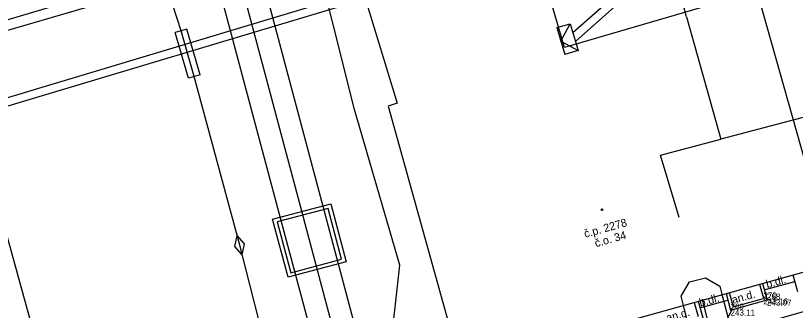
# Model space of a CAD drawing. Extents: x -599432 to -598680, y -1159407 to -1158632.
# Drawn here: x -599144.96 to -599106.02, y -1158898.71 to -1158883.97 of the extents above; entities that cross this region are included whole.
import ezdxf

# ---------------------------------------------------------------- set-up
doc = ezdxf.new("R2010")
doc.units = 0
for name, color, linetype in [('0004 VY - Body podrobné', 7, 'Continuous'), ('0005 VY - Body podrobné - čísla', 7, 'Continuous'), ('0006 VY - Body podrobné - výšky', 7, 'Continuous'), ('0007 ZA - Budova - zděná', 7, 'Continuous'), ('0009 TE - Budova - popis', 7, 'Continuous'), ('0010 ZA - Budova - označení', 7, 'Continuous'), ('0031 ZA - Ostatní rozhraní', 7, 'Continuous'), ('0032 TE - Popis povrchu', 7, 'Continuous'), ('0049 TE - Orientační _ popisná čísla', 7, 'Continuous'), ('0116 PV - budova převzatá z mapy', 7, 'Continuous'), ('0250 PV - TB - buňky', 7, 'Continuous'), ('0254 PV - TB - horkovod - vedení', 7, 'Continuous'), ('0255 PV - TB - horkovod - okraj', 7, 'Continuous'), ('0265 PV - TB - cizí síť vedení', 7, 'Continuous'), ('0266 PV - TB - cizí síť okraj', 7, 'Continuous'), ('0303 PV - RWE - NTL přípojka', 7, 'Continuous'), ('0308 PV - RWE - ochranné pásmo', 7, 'Continuous'), ('0350 PV - EON - buňky', 7, 'Continuous'), ('0352 PV - EON - NN', 7, 'Continuous'), ('0454 PV - O2 - kabel zaměřený', 7, 'Continuous'), ('0454 PV - PODA -  vedeni budoucnost', 7, 'Continuous'), ('0455 PV - O2 - kabel nezaměřený', 7, 'Continuous'), ('0551 PV - NETBOX - buňky', 7, 'Continuous'), ('0552 PV - NETBOX - vedení', 7, 'Continuous'), ('0553 PV - NETBOX - chranička', 7, 'Continuous')]:
    doc.layers.add(name, color=color, linetype=linetype)

# ---------------------------------------------------------------- blocks, each defined once
blk = doc.blocks.new('NN630')
at = {"layer": '0009 TE - Budova - popis'}
for points in [[(-0.003, -0.7), (-0.703, 0)], [(-0.703, -0.7), (-0.703, 0), (0.697, 0), (0.697, -0.7)], [(-0.003, -0.7), (0.697, 0)], [(-0.703, -0.7), (0.697, -0.7)]]:
    blk.add_lwpolyline(points, dxfattribs=at)

msp = doc.modelspace()

# ---------------------------------------------------------------- linework, layer by layer
at = {"layer": '0004 VY - Body podrobné'}
for p, q in [((-599106.03, -1158897.26), (-599106.03, -1158897.26)), ((-599107.62, -1158898.11), (-599107.62, -1158898.11)), ((-599107.44, -1158898.17), (-599107.44, -1158898.17)), ((-599109.26, -1158898.67), (-599109.26, -1158898.67))]:
    msp.add_line(p, q, dxfattribs=at)
at = {"layer": '0007 ZA - Budova - zděná'}
msp.add_line((-599122.72, -1158901.55), (-599062.29, -1158884.74), dxfattribs=at)
at = {"layer": '0010 ZA - Budova - označení'}
msp.add_circle((-599115.676, -1158893.68), 0.0438, dxfattribs=at)
at = {"layer": '0031 ZA - Ostatní rozhraní'}
for p, q in [((-599106.14, -1158896.938), (-599105.91, -1158897.767)), ((-599107.816, -1158897.404), (-599107.621, -1158898.107)), ((-599107.665, -1158897.362), (-599107.434, -1158898.191)), ((-599107.574, -1158897.689), (-599106.049, -1158897.265)), ((-599109.483, -1158897.868), (-599109.253, -1158898.697)), ((-599109.329, -1158897.825), (-599109.133, -1158898.528)), ((-599111.074, -1158898.31), (-599110.878, -1158899.014)), ((-599110.879, -1158898.256), (-599110.649, -1158899.085)), ((-599110.788, -1158898.584), (-599109.392, -1158898.195)), ((-599109.253, -1158898.697), (-599107.434, -1158898.191)), ((-599109.133, -1158898.531), (-599107.62, -1158898.11))]:
    msp.add_line(p, q, dxfattribs=at)
at = {"layer": '0032 TE - Popis povrchu'}
msp.add_line((-599109.68, -1158899.585), (-599109.146, -1158898.614), dxfattribs=at)
at = {"layer": '0116 PV - budova převzatá z mapy'}
for p, q in [((-599117.55, -1158885.56), (-599118.83, -1158881.17)), ((-599107.93, -1158882.74), (-599117.55, -1158885.56)), ((-599104.106, -1158896.372), (-599107.93, -1158882.74)), ((-599127.37, -1158883.54), (-599125.91, -1158888.34)), ((-599125.91, -1158888.34), (-599126.36, -1158888.49)), ((-599126.36, -1158888.49), (-599122.72, -1158901.55)), ((-599145.8, -1158893.59), (-599142.02, -1158907.12))]:
    msp.add_line(p, q, dxfattribs=at)
at = {"layer": '0250 PV - TB - buňky'}
for points in [[(-599132.129, -1158894.153), (-599129.224, -1158893.379), (-599128.45, -1158896.283), (-599131.354, -1158897.058), (-599132.129, -1158894.153)], [(-599131.221, -1158896.828), (-599128.68, -1158896.15), (-599129.357, -1158893.609), (-599131.899, -1158894.286), (-599131.221, -1158896.828)]]:
    msp.add_lwpolyline(points, dxfattribs=at)
at = {"layer": '0254 PV - TB - horkovod - vedení'}
msp.add_line((-599130.737, -1158893.547), (-599118.2, -1158940.655), dxfattribs=at)
at = {"layer": '0255 PV - TB - horkovod - okraj'}
for p, q in [((-599129.678, -1158893.249), (-599117.137, -1158940.372)), ((-599119.456, -1158940.213), (-599131.796, -1158893.845))]:
    msp.add_line(p, q, dxfattribs=at)
at = {"layer": '0265 PV - TB - cizí síť vedení'}
msp.add_lwpolyline([(-599093.332, -1158833.645), (-599087.354, -1158856.106), (-599137.173, -1158869.365), (-599130.737, -1158893.547)], dxfattribs=at)
at = {"layer": '0266 PV - TB - cizí síť okraj'}
for points in [[(-599092.269, -1158833.361), (-599086.008, -1158856.886), (-599135.827, -1158870.145), (-599129.678, -1158893.249)], [(-599131.796, -1158893.845), (-599138.519, -1158868.585), (-599088.7, -1158855.326), (-599094.395, -1158833.93)]]:
    msp.add_lwpolyline(points, dxfattribs=at)
at = {"layer": '0303 PV - RWE - NTL přípojka'}
msp.add_lwpolyline([(-599109.28, -1158903.4), (-599110.42, -1158899.1), (-599110.66, -1158898.15)], dxfattribs=at)
at = {"layer": '0308 PV - RWE - ochranné pásmo'}
msp.add_lwpolyline([(-599110.141, -1158904.057), (-599110.247, -1158903.656), (-599111.388, -1158899.351), (-599111.63, -1158898.395), (-599111.731, -1158897.993), (-599111.306, -1158897.281), (-599110.905, -1158897.18), (-599110.503, -1158897.079), (-599109.791, -1158897.504), (-599109.69, -1158897.905), (-599109.452, -1158898.849), (-599108.313, -1158903.144), (-599108.207, -1158903.544), (-599108.623, -1158904.261), (-599109.024, -1158904.367), (-599109.424, -1158904.473)], close=True, dxfattribs=at)
at = {"layer": '0352 PV - EON - NN'}
for points in [[(-599062.564, -1158867.124), (-599064.221, -1158867.572), (-599065.282, -1158867.859), (-599068.073, -1158869.751), (-599073.371, -1158871.463), (-599079.661, -1158873.298), (-599080.543, -1158872.51), (-599080.963, -1158873.779), (-599090.093, -1158876.254), (-599100.529, -1158879.074), (-599100.027, -1158880.841), (-599100.219, -1158880.896), (-599100.412, -1158880.951), (-599100.916, -1158879.178), (-599112.998, -1158882.403), (-599113.348, -1158881.982), (-599115.063, -1158882.464), (-599118.917, -1158878), (-599126.462, -1158879.719), (-599127.957, -1158880.989), (-599127.86, -1158882.798), (-599146.38, -1158888.373)], [(-599146.584, -1158888.851), (-599127.444, -1158883.09), (-599127.547, -1158881.165), (-599126.278, -1158880.087), (-599119.063, -1158878.444), (-599115.498, -1158882.572), (-599115.1, -1158883.033), (-599115.196, -1158883.118), (-599117.128, -1158884.834), (-599117.065, -1158885.046), (-599117.003, -1158885.259), (-599114.732, -1158883.24), (-599114.873, -1158882.827), (-599113.49, -1158882.438), (-599113.142, -1158882.855), (-599100.728, -1158879.542)]]:
    msp.add_lwpolyline(points, dxfattribs=at)
at = {"layer": '0454 PV - O2 - kabel zaměřený'}
msp.add_lwpolyline([(-599111.46, -1158884.03), (-599113.74, -1158875.43), (-599119.34, -1158876.95), (-599128.33, -1158879.73), (-599148.7, -1158885.68), (-599157.62, -1158887.91), (-599164.93, -1158889.99), (-599164.27, -1158892.4)], dxfattribs=at)
at = {"layer": '0454 PV - PODA -  vedeni budoucnost'}
msp.add_lwpolyline([(-599105.17, -1158898.649), (-599117.1, -1158902.075), (-599122.583, -1158904.816), (-599124.582, -1158905.375), (-599125.445, -1158902.506), (-599126.295, -1158901.085), (-599125.775, -1158896.452), (-599128.034, -1158888.659), (-599130.281, -1158879.673), (-599132.87, -1158880.447), (-599147.378, -1158884.773)], dxfattribs=at)
at = {"layer": '0455 PV - O2 - kabel nezaměřený'}
for points in [[(-599111.46, -1158884.03), (-599109.75, -1158890.15)], [(-599094.89, -1158886.23), (-599109.75, -1158890.15)], [(-599111.82, -1158894.06), (-599112.75, -1158890.94), (-599109.75, -1158890.15)]]:
    msp.add_lwpolyline(points, dxfattribs=at)
at = {"layer": '0551 PV - NETBOX - buňky'}
for points in [[(-599134.013, -1158895.516), (-599133.893, -1158894.966)], [(-599133.526, -1158895.384), (-599133.893, -1158894.966)], [(-599133.646, -1158895.935), (-599134.013, -1158895.516)], [(-599133.646, -1158895.935), (-599133.526, -1158895.384)]]:
    msp.add_lwpolyline(points, dxfattribs=at)
at = {"layer": '0552 PV - NETBOX - vedení'}
for points in [[(-599133.77, -1158895.45), (-599133.77, -1158895.45), (-599136.04, -1158887.02), (-599136.04, -1158887.02), (-599136.7, -1158884.73), (-599136.7, -1158884.73), (-599137.53, -1158882.14), (-599137.89, -1158881.7), (-599137.53, -1158882.14)], [(-599102.74, -1158899.21), (-599108.37, -1158900.95), (-599108.37, -1158900.95), (-599111.05, -1158901.6), (-599111.05, -1158901.6), (-599120.1, -1158903.98), (-599120.1, -1158903.98), (-599126.14, -1158905.33), (-599126.14, -1158905.33), (-599129.83, -1158906.27), (-599130.84, -1158906.53), (-599131.75, -1158903.39), (-599131.75, -1158903.39), (-599133.77, -1158895.45)]]:
    msp.add_lwpolyline(points, dxfattribs=at)
at = {"layer": '0553 PV - NETBOX - chranička'}
for points in [[(-599135.752, -1158886.937), (-599136.412, -1158884.647), (-599136.988, -1158884.813)], [(-599135.752, -1158886.937), (-599136.328, -1158887.103), (-599136.988, -1158884.813)]]:
    msp.add_lwpolyline(points, dxfattribs=at)

# ---------------------------------------------------------------- block references
at = {"layer": '0350 PV - EON - buňky', "rotation": -73.60693886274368}
msp.add_blockref('NN630', (-599117.065, -1158885.046), dxfattribs=at)

# ---------------------------------------------------------------- texts
at = {"layer": '0005 VY - Body podrobné - čísla'}
for s, p in [('270', (-599107.62, -1158898.11)), ('268', (-599107.44, -1158898.17)), ('269', (-599109.26, -1158898.67))]:
    msp.add_text(s, height=0.3, dxfattribs=at).set_placement(p)
at = {"layer": '0006 VY - Body podrobné - výšky'}
for s, p in [('243.16', (-599107.62, -1158898.41)), ('243.07', (-599107.44, -1158898.47)), ('243.11', (-599109.26, -1158898.97))]:
    msp.add_text(s, height=0.3, dxfattribs=at).set_placement(p)
at = {"layer": '0032 TE - Popis povrchu'}
for s, p in [('b.dl.', (-599107.427, -1158897.603)), ('b.dl.', (-599110.759, -1158898.531)), ('an.d.', (-599109.138, -1158898.386)), ('an.d.', (-599112.406, -1158899.29))]:
    msp.add_text(s, height=0.4, rotation=15.5451, dxfattribs=at).set_placement(p)
at = {"layer": '0049 TE - Orientační _ popisná čísla'}
for s, p in [('č.p. 2278', (-599116.514, -1158895.081)), ('č.o. 34', (-599115.981, -1158895.554))]:
    msp.add_text(s, height=0.4, rotation=15.6438, dxfattribs=at).set_placement(p)

doc.saveas('drawing.dxf')
